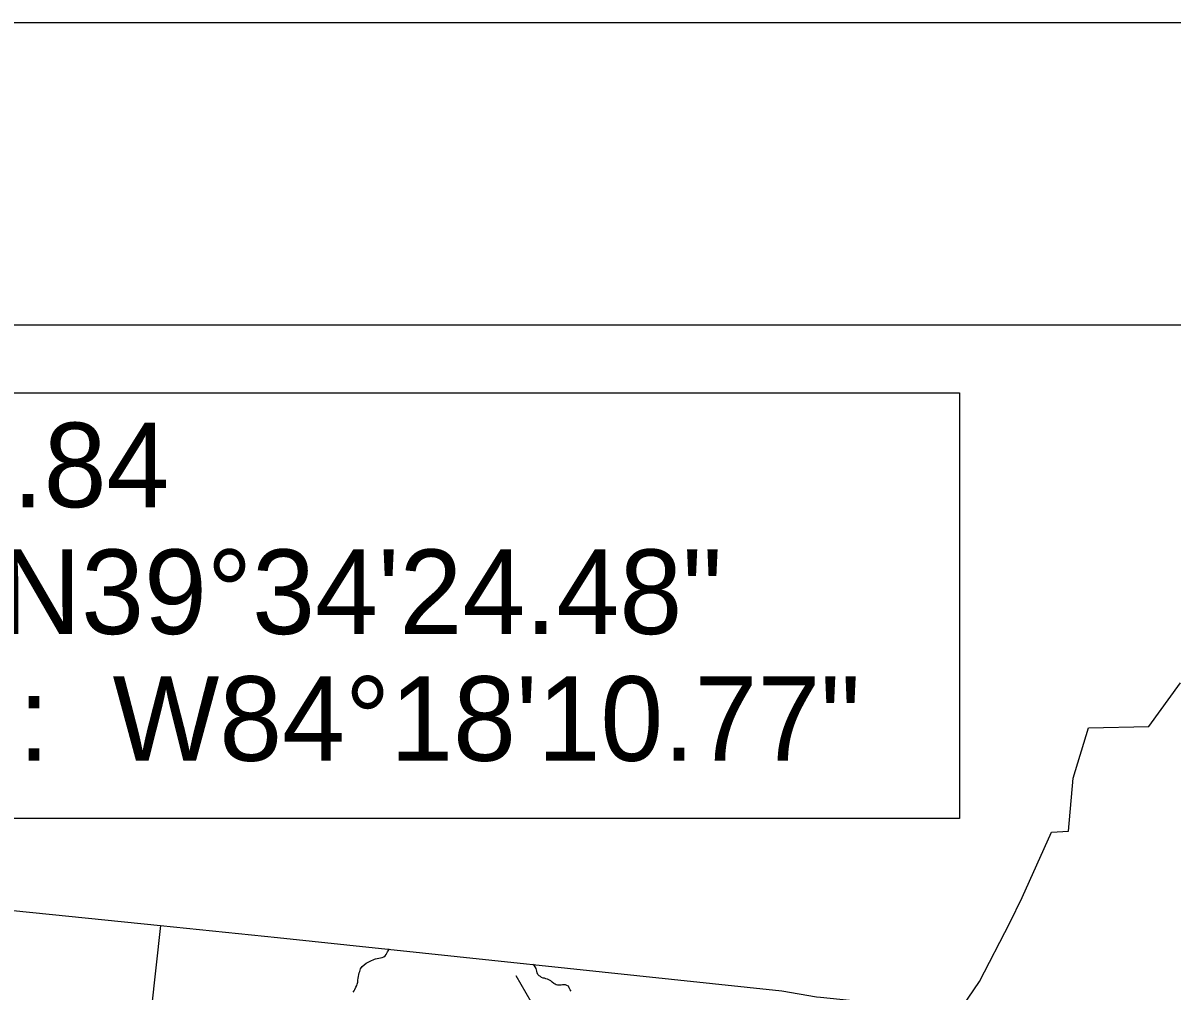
# Model space of a CAD drawing. Extents: x 0 to 1064, y 0 to 440.
# Drawn here: x 184.46 to 222.52, y 407.93 to 440 of the extents above; entities that cross this region are included whole.
import ezdxf

# ---------------------------------------------------------------- set-up
doc = ezdxf.new("R2010")
doc.units = 0
for name, color, linetype in [('GM_X_Corporation', 7, 'Continuous'), ('GM_X_County', 7, 'Continuous'), ('GM_X_Minor_River', 7, 'Continuous'), ('GM_X_Township', 7, 'Continuous'), ('GM_X_Township_Road', 7, 'Continuous'), ('GM_X_Township_Subdivision', 7, 'Continuous'), ('SH_Border', 7, 'Continuous'), ('SH_Cut_Line', 7, 'Continuous'), ('SH_Text', 7, 'Continuous')]:
    doc.layers.add(name, color=color, linetype=linetype)

msp = doc.modelspace()

# ---------------------------------------------------------------- linework, layer by layer
at = {"layer": 'GM_X_Corporation'}
msp.add_lwpolyline([(215.396, 407.143), (216.148, 408.248), (217.153, 410.19), (217.559, 411.029), (218.523, 413.194), (219.092, 413.224), (219.246, 414.98), (219.758, 416.655), (221.752, 416.69), (222.804, 418.138)], dxfattribs=at)
at = {"layer": 'GM_X_County'}
msp.add_lwpolyline([(179.238, 411.091), (189.014, 410.098), (192.884, 409.706), (209.593, 407.936), (210.747, 407.739), (210.88, 407.725), (215.136, 407.282), (226.594, 406.09)], dxfattribs=at)
at = {"layer": 'GM_X_Minor_River'}
for points in [[(195.395, 407.889), (195.426, 407.943), (195.452, 407.985), (195.484, 408.057), (195.515, 408.117), (195.528, 408.159), (195.548, 408.22), (195.555, 408.287), (195.563, 408.359), (195.57, 408.414), (195.584, 408.474), (195.591, 408.529), (195.616, 408.577), (195.642, 408.668), (195.699, 408.745), (195.755, 408.799), (195.829, 408.852), (195.896, 408.893), (195.957, 408.922), (196, 408.946), (196.056, 408.969), (196.098, 408.986), (196.141, 408.997), (196.196, 409.014), (196.251, 409.025), (196.306, 409.03), (196.361, 409.047), (196.416, 409.064), (196.459, 409.1), (196.49, 409.142), (196.509, 409.184), (196.535, 409.232), (196.578, 409.292), (196.604, 409.334)], [(202.124, 408.138), (202.082, 408.157), (202.04, 408.183), (201.993, 408.226), (201.939, 408.27), (201.879, 408.302), (201.837, 408.321), (201.783, 408.34), (201.735, 408.353), (201.692, 408.36), (201.638, 408.38), (201.596, 408.411), (201.554, 408.436), (201.513, 408.474), (201.49, 408.529), (201.479, 408.584), (201.468, 408.639), (201.463, 408.681), (201.374, 408.816)], [(202.617, 407.927), (202.588, 407.97), (202.553, 408.032), (202.524, 408.087), (202.476, 408.118), (202.434, 408.138), (202.379, 408.139), (202.325, 408.134), (202.282, 408.123), (202.227, 408.124), (202.167, 408.131), (202.124, 408.138)]]:
    msp.add_lwpolyline(points, dxfattribs=at)
at = {"layer": 'GM_X_Township'}
msp.add_lwpolyline([(179.238, 411.091), (189.014, 410.098), (192.884, 409.706), (209.593, 407.936), (210.747, 407.739)], dxfattribs=at)
at = {"layer": 'GM_X_Township_Road'}
msp.add_lwpolyline([(189.014, 410.099), (188.707, 407.294), (188.441, 405.346), (188.28, 403.543), (188.252, 403.252), (188.118, 401.98), (188.023, 401.292)], dxfattribs=at)
at = {"layer": 'GM_X_Township_Subdivision'}
msp.add_lwpolyline([(200.266, 400.584), (200.301, 401.005), (200.298, 401.292), (200.298, 401.509), (200.651, 404.485), (200.708, 404.587), (201.05, 404.67), (201.649, 404.869), (201.794, 405.085), (201.799, 405.553), (201.72, 406.6), (201.573, 407.029), (201.294, 407.57), (200.792, 408.438)], dxfattribs=at)
at = {"layer": 'SH_Border'}
msp.add_lwpolyline([(30, 430), (670, 430), (670, 10), (30, 10)], close=True, dxfattribs=at)
at = {"layer": 'SH_Cut_Line'}
msp.add_lwpolyline([(0, 0), (680, 0), (680, 440), (0, 440)], close=True, dxfattribs=at)
at = {"layer": 'SH_Text'}
msp.add_lwpolyline([(160.517, 427.751), (215.479, 427.751), (215.479, 413.642), (160.517, 413.642)], close=True, dxfattribs=at)

# ---------------------------------------------------------------- texts
for s, p in [('WAR-123-30.84', (162.462, 423.958)), ('LATITUDE:  N39°34\'24.48" ', (162.462, 419.758)), ('LONGITUDE:  W84°18\'10.77"', (162.462, 415.558))]:
    msp.add_text(s, height=2.8, dxfattribs=at).set_placement(p)

doc.saveas('drawing.dxf')
